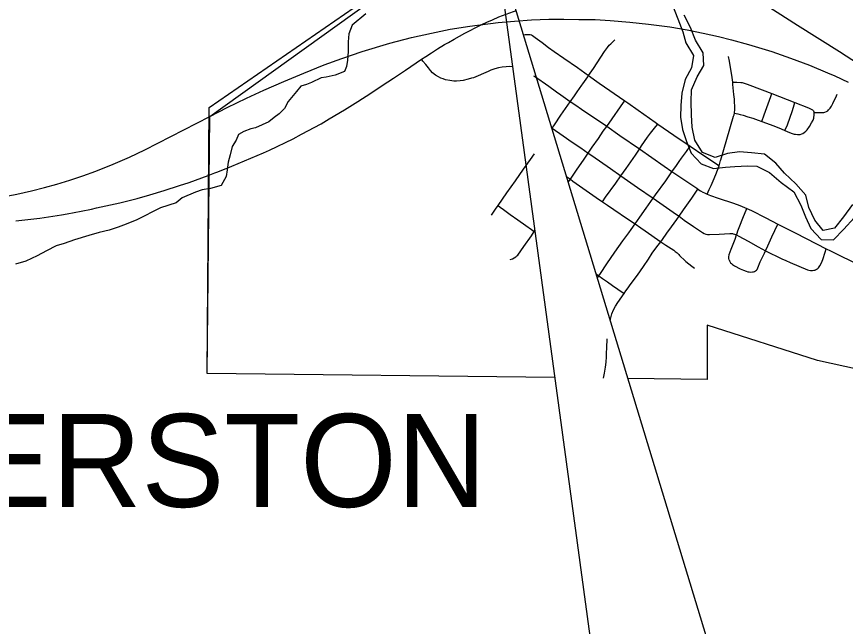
# Model space of a CAD drawing. Extents: x -1.2 to 34, y -8.5 to 22.
# Drawn here: x 6.085 to 6.93, y 16.749 to 17.37 of the extents above; entities that cross this region are included whole.
import ezdxf

# ---------------------------------------------------------------- set-up
doc = ezdxf.new("R2010")
doc.units = 0
for name, color, linetype in [('DV_X_Setback', 7, 'Continuous'), ('GM_X_City_Street', 7, 'Continuous'), ('GM_X_Corporation', 7, 'Continuous'), ('GM_X_Corporation_Text', 7, 'Continuous'), ('GM_X_County_Road', 7, 'Continuous'), ('GM_X_Major_River', 7, 'Continuous'), ('GM_X_Minor_River', 7, 'Continuous'), ('GM_X_Rail_Line', 7, 'Continuous'), ('GM_X_State_Route', 7, 'Continuous'), ('SH_Text', 7, 'Continuous')]:
    doc.layers.add(name, color=color, linetype=linetype)

msp = doc.modelspace()

# ---------------------------------------------------------------- linework, layer by layer
at = {"layer": 'DV_X_Setback'}
for points in [[(6.66466, 17.72061), (7.07051, 17.71401), (7.06564, 17.43663), (7.08807, 17.37038), (7.19167, 17.37389), (7.20134, 17.3773), (7.21014, 17.38339), (7.21454, 17.38765), (7.27966, 17.47898), (7.28103, 17.19972), (7.14063, 17.19982), (7.13979, 17.17173), (7.11851, 17.16837), (7.11522, 17.00016), (7.09057, 16.96156), (7.02721, 16.99211), (6.9019, 17.01941), (6.78917, 17.05541), (6.78917, 17.00026), (6.70852, 17.00122)], [(6.63393, 17.0021), (6.27953, 17.00631), (6.2821, 17.26837), (6.55734, 17.46602)]]:
    msp.add_lwpolyline(points, dxfattribs=at)
at = {"layer": 'GM_X_City_Street'}
for points in [[(6.60169, 17.35132), (6.60406, 17.35174), (6.60696, 17.35201), (6.60866, 17.35181), (6.61, 17.35139), (6.61129, 17.35074), (6.61404, 17.34891), (6.62097, 17.34383), (6.62746, 17.33873), (6.63314, 17.3345), (6.64315, 17.32761), (6.65699, 17.31806), (6.66844, 17.30998), (6.67926, 17.30241), (6.70541, 17.28421), (6.70834, 17.28215), (6.71884, 17.27486), (6.73609, 17.26259), (6.73908, 17.26053), (6.75521, 17.24935), (6.77182, 17.23801), (6.78598, 17.22863), (6.79883, 17.21989), (6.80144, 17.21812)], [(6.63115, 17.25609), (6.63135, 17.25638), (6.63349, 17.25972), (6.64023, 17.26961), (6.64967, 17.28326), (6.65389, 17.28935), (6.65669, 17.29342), (6.66137, 17.30006), (6.6626, 17.30172), (6.66749, 17.30864), (6.66844, 17.30998), (6.6732, 17.31711), (6.68461, 17.33441), (6.68759, 17.33865), (6.68944, 17.34104), (6.69096, 17.34244), (6.69349, 17.34478), (6.69526, 17.34638)], [(6.78929, 17.18919), (6.79146, 17.19388), (6.79341, 17.19794), (6.7955, 17.2027), (6.79812, 17.209), (6.80144, 17.21812), (6.80291, 17.22326), (6.80321, 17.22426), (6.80938, 17.24518), (6.81626, 17.26849), (6.81663, 17.26995), (6.8171, 17.27164), (6.81755, 17.27579), (6.81701, 17.28596), (6.81659, 17.29059), (6.81555, 17.30076), (6.81535, 17.30314), (6.8146, 17.30815), (6.81186, 17.32478), (6.81104, 17.32954)], [(6.81535, 17.30314), (6.81934, 17.30328), (6.82344, 17.30308), (6.82489, 17.30282), (6.82998, 17.30134), (6.83268, 17.30038), (6.85521, 17.29169), (6.8787, 17.28243), (6.89271, 17.27698), (6.89524, 17.27577), (6.89659, 17.27497), (6.89754, 17.27405), (6.89807, 17.27313), (6.89835, 17.27233)], [(6.84489, 17.26335), (6.84732, 17.26995), (6.85413, 17.28866), (6.85521, 17.29169)], [(6.88411, 17.24997), (6.88584, 17.25052), (6.88692, 17.25105), (6.88823, 17.25182), (6.88993, 17.25324), (6.89123, 17.2547), (6.89342, 17.25797), (6.8957, 17.26166), (6.89716, 17.26451), (6.89788, 17.26657), (6.89815, 17.26771), (6.89834, 17.26928), (6.89846, 17.27041), (6.89835, 17.27233), (6.90806, 17.27241), (6.90927, 17.27267), (6.91087, 17.27329), (6.91221, 17.27413), (6.91313, 17.27502), (6.91457, 17.27667), (6.91603, 17.27887), (6.91743, 17.28153), (6.92106, 17.28918), (6.9219, 17.29095)], [(6.64772, 17.20152), (6.64976, 17.20445), (6.6568, 17.2146), (6.66318, 17.2238), (6.66809, 17.23084), (6.67211, 17.23696), (6.67832, 17.24583), (6.68338, 17.25329), (6.68682, 17.25795), (6.69248, 17.26603), (6.70093, 17.27823), (6.70407, 17.28244), (6.70541, 17.28421)], [(6.86857, 17.25393), (6.87132, 17.25968), (6.87612, 17.27428), (6.87798, 17.28001), (6.8787, 17.28243)], [(6.8171, 17.27164), (6.82057, 17.27091), (6.82279, 17.27047), (6.82607, 17.26956), (6.83073, 17.26809), (6.83585, 17.26648), (6.84123, 17.26457), (6.84489, 17.26335), (6.85718, 17.25867), (6.86468, 17.25554), (6.86857, 17.25393), (6.87317, 17.25214), (6.87591, 17.25112), (6.87791, 17.25044), (6.87947, 17.25012), (6.88121, 17.24988), (6.88411, 17.24997)], [(6.631, 17.2566), (6.63135, 17.25638), (6.64256, 17.24863), (6.65158, 17.24224), (6.66032, 17.23629), (6.66809, 17.23084), (6.67155, 17.22852), (6.69087, 17.21518), (6.70134, 17.20777), (6.71827, 17.19599), (6.73422, 17.18496), (6.74101, 17.18044), (6.75802, 17.1685), (6.76059, 17.16669), (6.76591, 17.16269), (6.77539, 17.15621), (6.78458, 17.14993), (6.78613, 17.14895), (6.78773, 17.14826), (6.78945, 17.148), (6.7915, 17.14786), (6.80157, 17.14831), (6.81229, 17.14899), (6.81511, 17.14888), (6.81593, 17.14877), (6.81715, 17.14849), (6.81929, 17.14769), (6.82167, 17.14638), (6.83104, 17.14112), (6.84131, 17.13536), (6.84871, 17.13146), (6.86533, 17.12334), (6.86939, 17.1214), (6.87372, 17.11946), (6.89158, 17.11191), (6.89276, 17.11158), (6.89448, 17.11128), (6.89679, 17.11131), (6.89812, 17.11155), (6.89888, 17.11178)], [(6.68238, 17.18139), (6.68557, 17.18596), (6.69611, 17.20048), (6.70134, 17.20777), (6.7066, 17.21541), (6.71603, 17.229), (6.72011, 17.23487), (6.7224, 17.23826), (6.72851, 17.24721), (6.73154, 17.25134), (6.73697, 17.25808), (6.73908, 17.26053)], [(6.67742, 17.10369), (6.67879, 17.10574), (6.68048, 17.10819), (6.6869, 17.11816), (6.69526, 17.13002), (6.70338, 17.14157), (6.70927, 17.14969), (6.71169, 17.15312), (6.71585, 17.15877), (6.72044, 17.16556), (6.72705, 17.1749), (6.73422, 17.18496), (6.7366, 17.18835), (6.74701, 17.20283), (6.75335, 17.21184), (6.75783, 17.2182), (6.76072, 17.22231), (6.76318, 17.2258), (6.76807, 17.23277), (6.77182, 17.23801)], [(6.56939, 17.16772), (6.57352, 17.17367), (6.57608, 17.17739), (6.58507, 17.19032), (6.59379, 17.20286), (6.60212, 17.21474), (6.60909, 17.22456), (6.61316, 17.23026)], [(6.64608, 17.20692), (6.64686, 17.20637), (6.64976, 17.20445), (6.6524, 17.20252), (6.67622, 17.18555), (6.68238, 17.18139), (6.68768, 17.17793), (6.69407, 17.17352), (6.70811, 17.16397), (6.71585, 17.15877), (6.72165, 17.15483), (6.72619, 17.15166), (6.74191, 17.14068)], [(6.77978, 17.19418), (6.78253, 17.1926), (6.78492, 17.19128), (6.78652, 17.1905), (6.78929, 17.18919), (6.79276, 17.18778), (6.80041, 17.18514), (6.81606, 17.17994), (6.82256, 17.17751), (6.82957, 17.17464), (6.83444, 17.1723), (6.84919, 17.16484), (6.8613, 17.1587), (6.87977, 17.1495), (6.91049, 17.13354)], [(6.57608, 17.17739), (6.57817, 17.17589), (6.58161, 17.17343), (6.58844, 17.16855), (6.59607, 17.16309), (6.60443, 17.15711), (6.61012, 17.15303), (6.61299, 17.15098), (6.61382, 17.15041)], [(6.81765, 17.14326), (6.81929, 17.14769), (6.81988, 17.1494), (6.82069, 17.15179), (6.82244, 17.15673), (6.82551, 17.16472), (6.82957, 17.17464)], [(6.83755, 17.11032), (6.83862, 17.11101), (6.83943, 17.11165), (6.84009, 17.1124), (6.84078, 17.11388), (6.84338, 17.12), (6.84758, 17.12902), (6.84871, 17.13146), (6.85111, 17.13649), (6.85518, 17.14547), (6.8613, 17.1587)], [(6.58851, 17.1225), (6.59074, 17.12328), (6.59261, 17.12415), (6.59426, 17.12529), (6.59532, 17.12611), (6.59612, 17.12687), (6.60237, 17.13561), (6.61001, 17.14662), (6.61299, 17.15098), (6.61362, 17.15191)], [(6.74191, 17.14068), (6.74715, 17.13722), (6.75517, 17.13196), (6.7567, 17.13082), (6.75863, 17.12922), (6.7604, 17.12754), (6.76117, 17.1267), (6.76666, 17.12111), (6.76745, 17.12049), (6.77355, 17.11558), (6.77632, 17.11355)], [(6.81163, 17.12233), (6.81146, 17.12317), (6.81127, 17.12481), (6.8116, 17.1277), (6.81374, 17.13313), (6.81634, 17.13972), (6.81765, 17.14326)], [(6.89888, 17.11178), (6.89957, 17.11198), (6.90074, 17.11253), (6.90175, 17.11316), (6.90289, 17.11411), (6.90353, 17.115), (6.90425, 17.11598), (6.90552, 17.11831), (6.90648, 17.12067), (6.90712, 17.12268), (6.90953, 17.12998), (6.91049, 17.13354)], [(6.81163, 17.12233), (6.81199, 17.12122), (6.81264, 17.11985), (6.81316, 17.11915), (6.81405, 17.11827), (6.81519, 17.11746), (6.81724, 17.11612), (6.82298, 17.11296), (6.82622, 17.11155), (6.82911, 17.11052), (6.83058, 17.1101), (6.83211, 17.10988), (6.83385, 17.10977), (6.83555, 17.10987), (6.83656, 17.11003), (6.83755, 17.11032)], [(6.67627, 17.10748), (6.67879, 17.10574), (6.68251, 17.10316), (6.68768, 17.09959), (6.69281, 17.09604), (6.69825, 17.09227), (6.7046, 17.08788)]]:
    msp.add_lwpolyline(points, dxfattribs=at)
at = {"layer": 'GM_X_Corporation'}
for points in [[(6.63393, 17.0021), (6.27953, 17.00631), (6.28151, 17.27739), (6.55743, 17.46813)], [(7.28117, 17.40076), (7.28103, 17.19972), (7.14063, 17.19982), (7.13979, 17.17173), (7.11851, 17.16837), (7.11515, 17.02507), (7.11522, 17.00016), (7.09057, 16.96156), (7.02721, 16.99211), (6.9019, 17.01941), (6.78917, 17.05541), (6.78917, 17.00026), (6.70852, 17.00122)]]:
    msp.add_lwpolyline(points, dxfattribs=at)
at = {"layer": 'GM_X_County_Road'}
msp.add_line((6.91049, 17.13354), (6.91502, 17.13134), dxfattribs=at)
for points in [[(6.59095, 17.31901), (6.59074, 17.31905), (6.58739, 17.31923), (6.5842, 17.31905), (6.58027, 17.31865), (6.57652, 17.31791), (6.57294, 17.31689), (6.56884, 17.31543), (6.566, 17.31423), (6.55101, 17.30784), (6.54907, 17.3072), (6.54556, 17.3062), (6.54049, 17.30507), (6.53729, 17.30456), (6.53358, 17.30433), (6.53087, 17.30442), (6.52678, 17.30489), (6.52256, 17.30572), (6.51994, 17.30651), (6.51786, 17.30738), (6.51535, 17.30865), (6.51235, 17.31057), (6.50932, 17.31296), (6.50728, 17.31524), (6.50502, 17.31793), (6.50238, 17.32128), (6.49951, 17.32475), (6.49797, 17.32657)], [(6.77978, 17.19418), (6.75335, 17.21184), (6.74547, 17.21727), (6.72011, 17.23487), (6.70038, 17.24855), (6.68682, 17.25795), (6.66122, 17.27551), (6.65524, 17.27953), (6.64967, 17.28326), (6.64007, 17.28997), (6.63562, 17.29317), (6.62769, 17.29878), (6.61317, 17.30911), (6.61246, 17.30955)], [(6.69048, 17.06067), (6.6907, 17.06181), (6.69137, 17.06451), (6.69215, 17.06717), (6.69362, 17.07104), (6.69567, 17.07492), (6.69808, 17.07874), (6.7046, 17.08788), (6.70648, 17.09056), (6.70861, 17.09369), (6.71082, 17.09672), (6.71839, 17.10669), (6.72427, 17.11547), (6.72943, 17.12297), (6.73325, 17.129), (6.73796, 17.13556), (6.74191, 17.14068), (6.74367, 17.14298), (6.74822, 17.14925), (6.75281, 17.15571), (6.75819, 17.16331), (6.76059, 17.16669), (6.76509, 17.17303), (6.77375, 17.18504), (6.77783, 17.19105), (6.77978, 17.19418)], [(6.91502, 17.13134), (6.92099, 17.1284), (6.93988, 17.11916), (6.94959, 17.11443), (6.96141, 17.10871), (6.96841, 17.10525), (6.97958, 17.09972), (6.99057, 17.09429), (6.99144, 17.09387)], [(6.6835, 17.00152), (6.68448, 17.00657), (6.68556, 17.01289), (6.68617, 17.01796), (6.68648, 17.02319), (6.68705, 17.03618), (6.68716, 17.03789)], [(6.68716, 17.03789), (6.68725, 17.03907), (6.68744, 17.04179)]]:
    msp.add_lwpolyline(points, dxfattribs=at)
at = {"layer": 'GM_X_Major_River'}
for points in [[(6.75388, 17.38177), (6.75936, 17.3678), (6.76446, 17.35458), (6.76764, 17.34323), (6.77538, 17.33042), (6.77325, 17.31787), (6.76694, 17.30603), (6.76332, 17.29195), (6.76232, 17.27941), (6.76209, 17.26764), (6.76414, 17.25515), (6.76808, 17.24267), (6.77278, 17.23097), (6.78317, 17.22009), (6.79576, 17.21531), (6.80789, 17.21659), (6.81738, 17.21747), (6.83028, 17.218), (6.83978, 17.21773), (6.85277, 17.21106), (6.86466, 17.20096), (6.87769, 17.19163), (6.88469, 17.17805), (6.88939, 17.16597), (6.89485, 17.15427), (6.90562, 17.14302), (6.91815, 17.14241), (6.92865, 17.15354), (6.93915, 17.16505)], [(6.93746, 17.17869), (6.92812, 17.16605), (6.91915, 17.15456), (6.9074, 17.15214), (6.89892, 17.16267), (6.89307, 17.1755), (6.88988, 17.18798), (6.87949, 17.19962), (6.86797, 17.21049), (6.85911, 17.22062), (6.8476, 17.22997), (6.8343, 17.23133), (6.82213, 17.23232), (6.81, 17.23066), (6.79752, 17.22633), (6.78455, 17.23149), (6.7768, 17.24429), (6.77398, 17.25754), (6.77345, 17.27006), (6.77291, 17.28334), (6.77314, 17.29548), (6.77906, 17.30883), (6.78576, 17.3203), (6.78522, 17.3332), (6.77747, 17.346), (6.77238, 17.35885), (6.76577, 17.37167)]]:
    msp.add_lwpolyline(points, dxfattribs=at)
at = {"layer": 'GM_X_Minor_River'}
msp.add_lwpolyline([(6.44111, 17.37297), (6.42727, 17.36134), (6.42399, 17.35253), (6.42334, 17.34453), (6.42311, 17.33462), (6.42247, 17.32585), (6.42143, 17.31936), (6.41961, 17.314), (6.40982, 17.31043), (6.40076, 17.30839), (6.39585, 17.30755), (6.3857, 17.30283), (6.3808, 17.30085), (6.37515, 17.29924), (6.37068, 17.29384), (6.36212, 17.28343), (6.35843, 17.27652), (6.35283, 17.2711), (6.34796, 17.26722), (6.34235, 17.26295), (6.32881, 17.25665), (6.3239, 17.25582), (6.31674, 17.25304), (6.31149, 17.24991), (6.30892, 17.24416), (6.30485, 17.23763), (6.30307, 17.22922), (6.30091, 17.22157), (6.29989, 17.21394), (6.29885, 17.20707), (6.29368, 17.19786), (6.28274, 17.19503), (6.27443, 17.19338), (6.26765, 17.19099), (6.2541, 17.18545), (6.24773, 17.18041), (6.23191, 17.17522), (6.20785, 17.16305), (6.19693, 17.15869), (6.18864, 17.15552), (6.1796, 17.15234), (6.16942, 17.1499), (6.15885, 17.14707), (6.14415, 17.14266), (6.1336, 17.13869), (6.12569, 17.13629), (6.11554, 17.13118), (6.10615, 17.12609), (6.09448, 17.12097), (6.08393, 17.11776)], dxfattribs=at)
at = {"layer": 'GM_X_Rail_Line'}
for points in [[(6.59383, 17.54435), (6.64675, 17.51055), (6.81923, 17.40161), (6.88127, 17.36152), (6.9242, 17.33447), (6.96278, 17.30932), (6.99361, 17.28795), (7.04374, 17.24826), (7.09404, 17.20908), (7.12317, 17.1879)], [(6.06943, 17.18591), (6.0855, 17.18922), (6.10035, 17.19253), (6.11378, 17.19574), (6.12635, 17.19924), (6.13931, 17.20322), (6.15283, 17.20766), (6.16607, 17.21248), (6.18366, 17.21958), (6.20021, 17.22676), (6.21581, 17.23414), (6.2821, 17.26837), (6.29998, 17.27754), (6.31946, 17.287), (6.33723, 17.29523), (6.35757, 17.30412), (6.3779, 17.31253), (6.3988, 17.32095), (6.41667, 17.32738), (6.43757, 17.33457), (6.46575, 17.34308), (6.48788, 17.34875), (6.50821, 17.35329), (6.5274, 17.35717), (6.54736, 17.36019), (6.57601, 17.36426), (6.59275, 17.36558), (6.61024, 17.36672), (6.62783, 17.36757), (6.64325, 17.36766), (6.65836, 17.36726), (6.67521, 17.367), (6.69025, 17.36625), (6.71029, 17.36454), (6.72959, 17.36246), (6.75115, 17.35963), (6.76902, 17.35651), (6.7851, 17.3531), (6.80098, 17.3497), (6.81403, 17.34639), (6.83143, 17.34156), (6.85517, 17.33438), (6.87418, 17.32776), (6.89366, 17.32048), (6.912, 17.31272), (6.91947, 17.3096), (6.933, 17.30327)]]:
    msp.add_lwpolyline(points, dxfattribs=at)
at = {"layer": 'GM_X_State_Route'}
for points in [[(6.48159, 17.3156), (6.49797, 17.32657), (6.50258, 17.32953), (6.50829, 17.33328), (6.51446, 17.33733), (6.5214, 17.34152), (6.52549, 17.34374), (6.53116, 17.34703), (6.53668, 17.35031), (6.54203, 17.3532), (6.54634, 17.35543), (6.55421, 17.35938), (6.55959, 17.36197), (6.56464, 17.36433), (6.57042, 17.36692), (6.57699, 17.36971), (6.58423, 17.3725), (6.59164, 17.37529), (6.5939, 17.37609)], [(6.28946, 17.21154), (6.29891, 17.21525), (6.30235, 17.21661), (6.30461, 17.21752), (6.33697, 17.23118), (6.34316, 17.23401), (6.36721, 17.24568), (6.37582, 17.25012), (6.39568, 17.26094), (6.40395, 17.26577), (6.41966, 17.2752), (6.43298, 17.28357), (6.44625, 17.29204), (6.45801, 17.29984), (6.4693, 17.30738), (6.48159, 17.3156)], [(6.08432, 17.16179), (6.10289, 17.16387), (6.10904, 17.16469), (6.13096, 17.16813), (6.13674, 17.16914), (6.15097, 17.17184), (6.16147, 17.17393), (6.16677, 17.17506), (6.19052, 17.18043), (6.20812, 17.18482), (6.22116, 17.18855), (6.23578, 17.19295), (6.25131, 17.19784), (6.26104, 17.20107), (6.28055, 17.2081), (6.28728, 17.21069), (6.28946, 17.21154)]]:
    msp.add_lwpolyline(points, dxfattribs=at)
at = {"layer": 'SH_Text'}
msp.add_lwpolyline([(6.79053, 16.73104), (6.57392, 17.44466), (6.67069, 16.73104)], dxfattribs=at)

# ---------------------------------------------------------------- texts
at = {"layer": 'GM_X_Corporation_Text'}
msp.add_text('BOWERSTON', height=0.094697, rotation=0.00001, dxfattribs=at).set_placement((5.73411, 16.87032))

doc.saveas('drawing.dxf')
